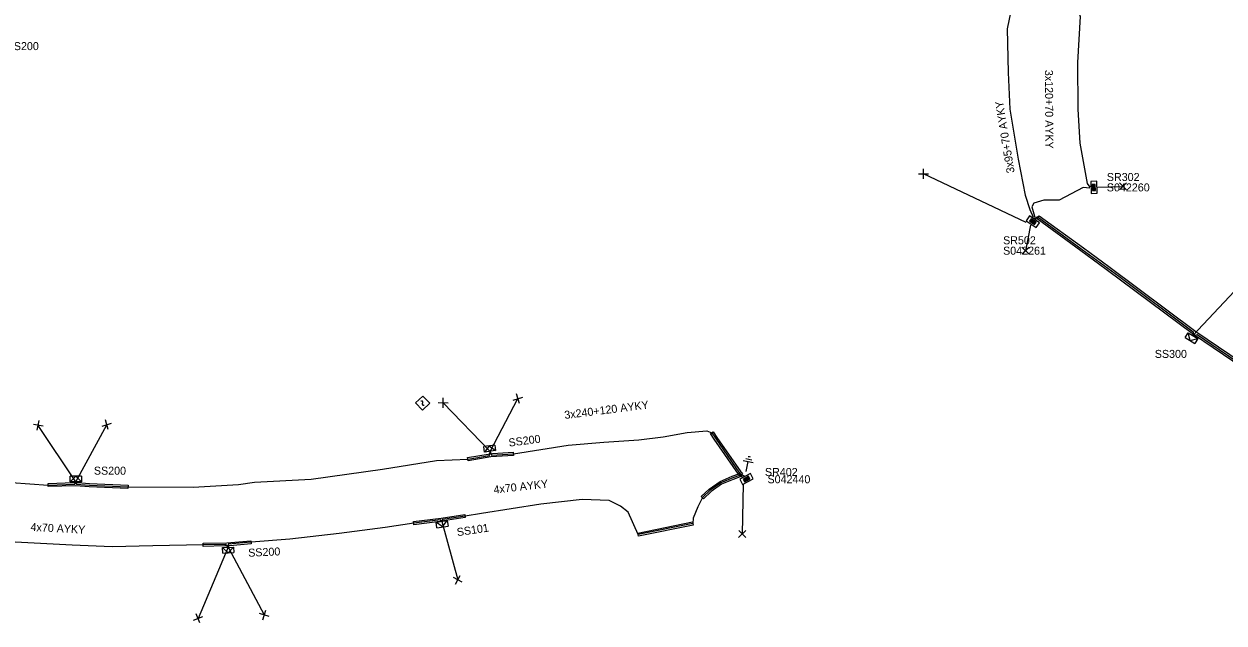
# Model space of a CAD drawing. Extents: x -748492 to -735633, y -1146251 to -1139940.
# Drawn here: x -736921.6 to -736771.7, y -1145081.1 to -1145006.2 of the extents above; entities that cross this region are included whole.
import ezdxf

# ---------------------------------------------------------------- set-up
doc = ezdxf.new("R2010")
doc.units = 0
for name, color, linetype in [('Vrstva 1', 7, 'Continuous'), ('Vrstva 14', 7, 'Continuous'), ('Vrstva 15', 7, 'Continuous'), ('Vrstva 20', 7, 'Continuous'), ('Vrstva 28', 7, 'Continuous'), ('Vrstva 29', 7, 'Continuous'), ('Vrstva 30', 7, 'Continuous'), ('Vrstva 31', 7, 'Continuous'), ('Vrstva 33', 7, 'Continuous'), ('Vrstva 34', 7, 'Continuous'), ('Vrstva 5', 7, 'Continuous'), ('Vrstva 59', 7, 'Continuous'), ('Vrstva 6', 7, 'Continuous'), ('Vrstva 8', 7, 'Continuous'), ('Vrstva 9', 7, 'Continuous')]:
    doc.layers.add(name, color=color, linetype=linetype)

# ---------------------------------------------------------------- blocks, each defined once
blk = doc.blocks.new('NN800')
at = {"layer": 'Vrstva 1'}
for points in [[(-0.44, 0.44), (0.44, -0.44)], [(-0.44, -0.44), (0.44, 0.44)]]:
    blk.add_lwpolyline(points, dxfattribs=at)
blk = doc.blocks.new('NN620')
at = {"layer": 'Vrstva 8'}
for points in [[(0.75, 0), (-0.75, 0)], [(-0.75, 0), (-0.75, -0.75)], [(0.75, -0.75), (0.75, 0)], [(-0.75, -0.75), (0.75, -0.75)], [(0.37, -0.18), (-0.38, -0.18)], [(-0.38, -0.18), (-0.38, -0.56)], [(-0.38, -0.56), (0.37, -0.56)], [(0.32, -0.23), (-0.33, -0.23)], [(-0.33, -0.23), (-0.33, -0.51)], [(-0.33, -0.51), (0.32, -0.51)], [(0.27, -0.27), (-0.28, -0.27)], [(-0.28, -0.27), (-0.28, -0.46)], [(-0.28, -0.46), (0.27, -0.46)], [(0.23, -0.32), (-0.23, -0.32)], [(-0.23, -0.32), (-0.23, -0.42)], [(-0.23, -0.42), (0.23, -0.42)], [(-0.19, -0.37), (0.19, -0.37)], [(0.23, -0.42), (0.23, -0.32)], [(0.27, -0.46), (0.27, -0.27)], [(0.32, -0.51), (0.32, -0.23)], [(0.37, -0.56), (0.37, -0.18)]]:
    blk.add_lwpolyline(points, dxfattribs=at)
blk = doc.blocks.new('NN630')
at = {"layer": 'Vrstva 9'}
for points in [[(0, -0.7), (-0.7, 0)], [(-0.7, -0.7), (-0.7, 0), (0.7, 0), (0.7, -0.7)], [(-0.7, -0.7), (0.7, -0.7)], [(0, -0.7), (0.7, 0)]]:
    blk.add_lwpolyline(points, dxfattribs=at)
blk = doc.blocks.new('NN810')
at = {"layer": 'Vrstva 14'}
for points in [[(0, -0.64), (0, -1.89)], [(0.63, -1.89), (-0.62, -1.89)], [(0.39, -2.2), (-0.4, -2.2)], [(0, -2.52), (-0.12, -2.52)], [(0.14, -2.52), (0, -2.52)]]:
    blk.add_lwpolyline(points, dxfattribs=at)
blk = doc.blocks.new('NN740')
at = {"layer": 'Vrstva 1'}
for points in [[(0.62, 0.62), (-0.63, 0.62)], [(-0.63, 0.62), (-0.63, -0.63)], [(0, 0), (0, 0.01), (0, 0.03), (-0.01, 0.05), (-0.01, 0.06), (-0.02, 0.08), (-0.03, 0.09), (-0.04, 0.1), (-0.05, 0.11), (-0.06, 0.12), (-0.08, 0.13), (-0.09, 0.14), (-0.11, 0.14), (-0.12, 0.15), (-0.14, 0.15), (-0.15, 0.15), (-0.17, 0.15), (-0.18, 0.15), (-0.2, 0.15), (-0.21, 0.14), (-0.23, 0.13), (-0.24, 0.12), (-0.26, 0.11), (-0.27, 0.1), (-0.28, 0.09), (-0.29, 0.08), (-0.29, 0.06), (-0.3, 0.05), (-0.3, 0.03), (-0.31, 0.02), (-0.31, 0), (-0.31, 0)], [(0.62, -0.63), (0.62, 0.62)], [(-0.63, -0.63), (0.62, -0.63)], [(0, 0), (0, -0.02), (0, -0.03), (0.01, -0.05), (0.01, -0.06), (0.02, -0.08), (0.03, -0.09), (0.04, -0.1), (0.05, -0.11), (0.06, -0.12), (0.07, -0.13), (0.09, -0.14), (0.1, -0.15), (0.12, -0.15), (0.13, -0.15), (0.15, -0.15), (0.16, -0.15), (0.18, -0.15), (0.19, -0.15), (0.21, -0.14), (0.22, -0.14), (0.24, -0.13), (0.25, -0.12), (0.26, -0.11), (0.27, -0.09), (0.28, -0.08), (0.29, -0.07), (0.29, -0.05), (0.3, -0.04), (0.3, -0.02), (0.3, -0.01), (0.3, -0.01)]]:
    blk.add_lwpolyline(points, dxfattribs=at)

msp = doc.modelspace()

# ---------------------------------------------------------------- linework, layer by layer
at = {"layer": 'Vrstva 20'}
for points in [[(-736795.01, -1145030.55), (-736794.74, -1145030.17), (-736789.22, -1145034.17), (-736786.07, -1145036.48), (-736775.17, -1145044.6), (-736765.38, -1145051.24), (-736757.51, -1145056.15), (-736753.08, -1145058.92), (-736745.49, -1145063.64), (-736745.75, -1145064.06), (-736753.34, -1145059.34), (-736757.77, -1145056.57), (-736765.66, -1145051.66), (-736775.46, -1145045.01), (-736786.37, -1145036.88), (-736789.54, -1145034.55)], [(-736835.81, -1145057.38), (-736835.47, -1145057.16), (-736835.03, -1145057.86), (-736832.04, -1145062.17), (-736831.8, -1145062.32), (-736832.02, -1145062.66), (-736832.32, -1145062.47), (-736835.37, -1145058.08)], [(-736860.45, -1145059.71), (-736860.43, -1145060.11), (-736863.24, -1145060.28), (-736866.1, -1145060.77), (-736866.16, -1145060.37), (-736863.6, -1145059.95), (-736863.04, -1145059.87)], [(-736918.53, -1145064.01), (-736918.55, -1145063.61), (-736915.34, -1145063.5), (-736914.84, -1145063.51), (-736913.39, -1145063.64), (-736908.57, -1145063.83), (-736908.59, -1145064.23), (-736913.41, -1145064.04), (-736915.08, -1145063.9)], [(-736836.69, -1145065.54), (-736836.97, -1145065.24), (-736835.97, -1145064.31), (-736834.62, -1145063.35), (-736833.1, -1145062.72), (-736832.26, -1145062.41), (-736832.12, -1145062.79), (-736832.96, -1145063.1), (-736834.42, -1145063.71), (-736835.71, -1145064.62)], [(-736872.85, -1145068.77), (-736872.91, -1145068.37), (-736869.45, -1145067.94), (-736866.5, -1145067.49), (-736866.44, -1145067.89), (-736869.16, -1145068.3), (-736869.63, -1145068.36)], [(-736844.81, -1145070.21), (-736844.89, -1145069.81), (-736838.07, -1145068.42), (-736837.99, -1145068.82)], [(-736899.19, -1145071.49), (-736899.19, -1145071.09), (-736896.24, -1145071.03), (-736893.22, -1145070.77), (-736893.18, -1145071.17), (-736895.86, -1145071.4), (-736896.46, -1145071.43)]]:
    msp.add_lwpolyline(points, close=True, dxfattribs=at)
at = {"layer": 'Vrstva 5'}
for points in [[(-736777.51, -1144963.56), (-736778.15, -1144963.77), (-736778.68, -1144964.65), (-736780.47, -1144969.39), (-736782.18, -1144974.95), (-736785.28, -1144984.42), (-736785.45, -1144985.52), (-736786.51, -1144989.79), (-736785.04, -1144990.49), (-736786.71, -1144990.72), (-736787.37, -1144992.62), (-736788.91, -1144998.47), (-736789.46, -1144999.84), (-736790.02, -1145002.13), (-736790.18, -1145003.61), (-736789.64, -1145005.23), (-736789.96, -1145010.99), (-736789.92, -1145016.81), (-736789.69, -1145021.06), (-736788.76, -1145026.14), (-736788.42, -1145026.56)], [(-736793.65, -1144984.05), (-736793.31, -1144984.4), (-736794.05, -1144988.62), (-736794.92, -1144992.15), (-736797.35, -1145000.58), (-736797.97, -1145003.07), (-736798.39, -1145003.21), (-736798.09, -1145003.59), (-736798.76, -1145006.78), (-736798.63, -1145012.23), (-736798.41, -1145016.81), (-736797.38, -1145023.1), (-736796.51, -1145027.6), (-736795.9, -1145029.36), (-736795.5, -1145030.33)], [(-736788.42, -1145026.69), (-736789.26, -1145026.61), (-736792.24, -1145028.21), (-736794.17, -1145028.22), (-736795.43, -1145028.58), (-736795.69, -1145029.04), (-736795.25, -1145030.48)], [(-736795.15, -1145030.56), (-736795, -1145030.24), (-736789.38, -1145034.36), (-736784.8, -1145037.72), (-736775.53, -1145044.65), (-736775.55, -1145045.14), (-736775.03, -1145045), (-736772.26, -1145046.89), (-736765.52, -1145051.45), (-736757.64, -1145056.36), (-736745.89, -1145063.66), (-736746.23, -1145064.54), (-736745.62, -1145063.85), (-736738.12, -1145068.38), (-736733.09, -1145071.72), (-736733.76, -1145072.49), (-736736.53, -1145077.55), (-736735.95, -1145078.23)], [(-736923.12, -1145063.49), (-736918.54, -1145063.81), (-736915.21, -1145063.7), (-736915.09, -1145063.42), (-736914.99, -1145063.7), (-736913.4, -1145063.84), (-736908.58, -1145064.03), (-736900.43, -1145064.08), (-736894.79, -1145063.74), (-736892.79, -1145063.44), (-736885.69, -1145063.09), (-736876.8, -1145061.81), (-736870.05, -1145060.74), (-736866.13, -1145060.57), (-736863.42, -1145060.12), (-736863.35, -1145059.6), (-736863.18, -1145060.08), (-736860.44, -1145059.91), (-736853.57, -1145058.84), (-736849.12, -1145058.45), (-736844.78, -1145058.16), (-736841.74, -1145057.78), (-736838.72, -1145057.24), (-736836.27, -1145057.03), (-736835.64, -1145057.27), (-736835.2, -1145057.97), (-736832.18, -1145062.32), (-736831.5, -1145062.76)], [(-736831.77, -1145062.89), (-736832.19, -1145062.6), (-736833.03, -1145062.91), (-736834.52, -1145063.53), (-736835.84, -1145064.47), (-736836.83, -1145065.39), (-736837.39, -1145066.53), (-736837.97, -1145067.94), (-736838.03, -1145068.62), (-736844.85, -1145070.01), (-736846.11, -1145067.19), (-736847.05, -1145066.47), (-736848.48, -1145065.75), (-736851.83, -1145065.61), (-736857.01, -1145066.2), (-736864.42, -1145067.37), (-736866.47, -1145067.69), (-736869.3, -1145068.12), (-736869.39, -1145068.35), (-736869.54, -1145068.15), (-736872.88, -1145068.57), (-736876.45, -1145069.13), (-736882.18, -1145069.87), (-736888.34, -1145070.57), (-736893.2, -1145070.97), (-736896.05, -1145071.21), (-736896.08, -1145071.59), (-736896.36, -1145071.23), (-736899.19, -1145071.29), (-736905.46, -1145071.41), (-736910.54, -1145071.54), (-736915.55, -1145071.33), (-736923.47, -1145070.91)]]:
    msp.add_lwpolyline(points, dxfattribs=at)
at = {"layer": 'Vrstva 59'}
for points in [[(-736796.39, -1145030.98), (-736809.2, -1145024.9)], [(-736787.41, -1145026.59), (-736784.29, -1145026.48)], [(-736775.55, -1145045.14), (-736761.25, -1145029.88)], [(-736795.83, -1145031.31), (-736796.46, -1145034.53)], [(-736863.35, -1145059.6), (-736859.86, -1145053.01)], [(-736863.35, -1145059.6), (-736869.2, -1145053.55)], [(-736915.09, -1145063.42), (-736919.78, -1145056.35)], [(-736915.09, -1145063.42), (-736911.22, -1145056.27)], [(-736831.75, -1145063.66), (-736831.85, -1145069.94)], [(-736869.39, -1145068.35), (-736867.37, -1145075.66)], [(-736896.08, -1145071.59), (-736899.82, -1145080.48)], [(-736896.08, -1145071.59), (-736891.55, -1145080.05)]]:
    msp.add_lwpolyline(points, dxfattribs=at)

# ---------------------------------------------------------------- block references
at = {"layer": 'Vrstva 15', "rotation": 168.26382784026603}
msp.add_blockref('NN810', (-736831.48, -1145062.73), dxfattribs=at)
at = {"layer": 'Vrstva 28'}
for p, rotation in [((-736788.29, -1145026.62), 91.94514718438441), ((-736795.33, -1145030.59), -34.95169166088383), ((-736831.48, -1145062.73), 27.328833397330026)]:
    msp.add_blockref('NN620', p, dxfattribs=dict(at, rotation=rotation))
at = {"layer": 'Vrstva 31'}
for p, rotation in [((-736775.55, -1145045.14), -30.927277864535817), ((-736863.35, -1145059.6), -172.59316110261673), ((-736915.09, -1145063.42), 179.7908249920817), ((-736869.39, -1145068.35), 8.49844442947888), ((-736896.08, -1145071.59), 2.6025138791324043)]:
    msp.add_blockref('NN630', p, dxfattribs=dict(at, rotation=rotation))
at = {"layer": 'Vrstva 34'}
for name, p, rotation in [('NN800', (-736809.2, -1145024.9), 44.99999995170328), ('NN740', (-736871.78, -1145053.57), 134.0372277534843), ('NN800', (-736869.2, -1145053.55), 134.0372277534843), ('NN800', (-736859.86, -1145053.01), 62.094877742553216), ('NN800', (-736919.78, -1145056.35), 123.55909153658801), ('NN800', (-736911.22, -1145056.27), 61.575155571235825), ('NN800', (-736831.85, -1145069.94), 89.08775834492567), ('NN800', (-736867.37, -1145075.66), 105.44718886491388), ('NN800', (-736899.82, -1145080.48), 67.18351944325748), ('NN800', (-736891.55, -1145080.05), 118.16723336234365)]:
    msp.add_blockref(name, p, dxfattribs=dict(at, rotation=rotation))
for p in [(-736784.29, -1145026.48), (-736796.46, -1145034.53)]:
    msp.add_blockref('NN800', p, dxfattribs=at)

# ---------------------------------------------------------------- texts
at = {"layer": 'Vrstva 29'}
for s, p in [('S042260', (-736786.3, -1145027.11)), ('S042261', (-736799.26, -1145035.02)), ('S042440', (-736828.69, -1145063.59))]:
    msp.add_text(s, height=1, dxfattribs=at).set_placement(p)
at = {"layer": 'Vrstva 30'}
for s, p in [('SR302', (-736786.3, -1145025.81)), ('SR502', (-736799.26, -1145033.72)), ('SR402', (-736829.01, -1145062.68))]:
    msp.add_text(s, height=1, dxfattribs=at).set_placement(p)
at = {"layer": 'Vrstva 33'}
for s, p in [('SS200', (-736923.73, -1145009.45)), ('SS300', (-736780.31, -1145047.92))]:
    msp.add_text(s, height=1, dxfattribs=at).set_placement(p)
for s, rotation, p in [('SS200', 7.407, (-736860.97, -1145059.02)), ('SS200', 359.791, (-736912.84, -1145062.51)), ('SS101', 8.498, (-736867.42, -1145070.21)), ('SS200', 2.603, (-736893.54, -1145072.78))]:
    msp.add_text(s, height=1, rotation=rotation, dxfattribs=at).set_placement(p)
at = {"layer": 'Vrstva 6'}
for s, rotation, p in [('3x120+70 AYKY', 270.297, (-736794.03, -1145011.92)), ('3x95+70 AYKY', 99.3, (-736797.81, -1145024.74)), ('3x240+120 AYKY', 7.125, (-736854, -1145055.56)), ('4x70 AYKY', 6.498, (-736862.85, -1145064.89)), ('4x70 AYKY', 356.964, (-736920.77, -1145069.54))]:
    msp.add_text(s, height=1, rotation=rotation, dxfattribs=at).set_placement(p)

doc.saveas('drawing.dxf')
